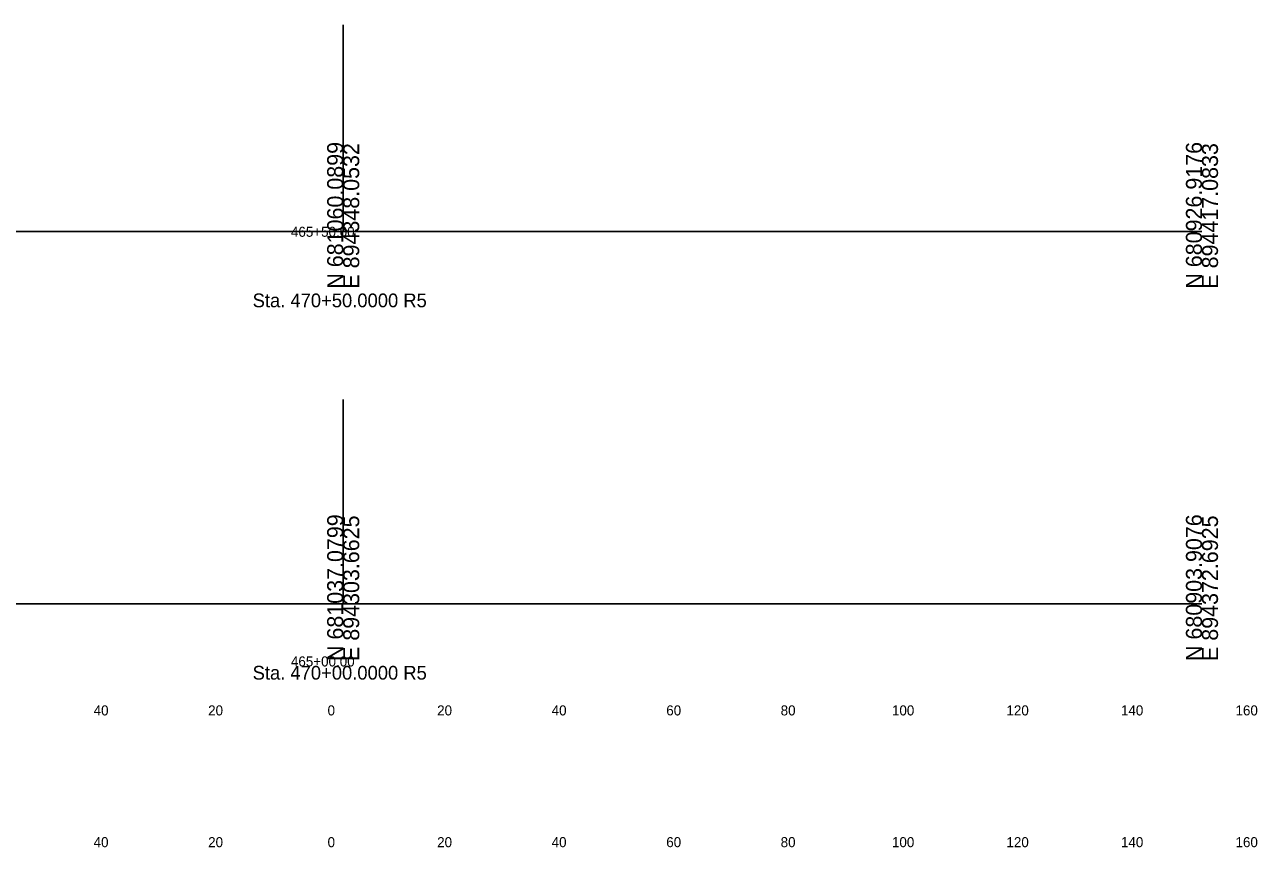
# Model space of a CAD drawing. Extents: x 21059 to 22955, y 6470 to 17494.
# Drawn here: x 21589.2 to 21804.5, y 9442.3 to 9585.9 of the extents above; entities that cross this region are included whole.
import ezdxf

# ---------------------------------------------------------------- set-up
doc = ezdxf.new("R2010")
doc.units = 0
for name, color, linetype in [('Draft_XS_Text', 7, 'Continuous'), ('DTM CONTOURS_MAJOR', 7, 'Continuous'), ('SLOPE_STAKES_FILL', 7, 'Continuous'), ('X_PROFILES_1', 7, 'Continuous')]:
    doc.layers.add(name, color=color, linetype=linetype)

msp = doc.modelspace()

# ---------------------------------------------------------------- linework, layer by layer
at = {"layer": 'DTM CONTOURS_MAJOR'}
for p, q in [((21644.84, 9549.84), (21644.84, 9585.92)), ((21494.84, 9549.84), (21644.84, 9549.84)), ((21644.84, 9549.84), (21794.84, 9549.84)), ((21644.84, 9484.84), (21644.84, 9520.47)), ((21494.84, 9484.84), (21644.84, 9484.84)), ((21644.84, 9484.84), (21794.84, 9484.84))]:
    msp.add_line(p, q, dxfattribs=at)

# ---------------------------------------------------------------- texts
at = {"layer": 'Draft_XS_Text'}
for s, p in [('  40  ', (21599.95, 9465.34)), ('  20  ', (21619.95, 9465.34)), ('  0  ', (21640.81, 9465.34)), ('  0  ', (21640.81, 9465.34)), ('  20  ', (21659.95, 9465.34)), ('  40  ', (21679.95, 9465.34)), ('  60  ', (21699.97, 9465.34)), ('  80  ', (21719.95, 9465.34)), ('  100  ', (21739.39, 9465.34)), ('  120  ', (21759.39, 9465.34)), ('  140  ', (21779.39, 9465.34)), ('  160  ', (21799.4, 9465.34)), ('  40  ', (21599.95, 9442.34)), ('  20  ', (21619.95, 9442.34)), ('  0  ', (21640.81, 9442.34)), ('  0  ', (21640.81, 9442.34)), ('  20  ', (21659.95, 9442.34)), ('  40  ', (21679.95, 9442.34)), ('  60  ', (21699.97, 9442.34)), ('  80  ', (21719.95, 9442.34)), ('  100  ', (21739.39, 9442.34)), ('  120  ', (21759.39, 9442.34)), ('  140  ', (21779.39, 9442.34)), ('  160  ', (21799.4, 9442.34))]:
    msp.add_text(s, height=1.75, dxfattribs=at).set_placement(p)
at = {"layer": 'DTM CONTOURS_MAJOR'}
for s, p in [('N 681060.0899', (21644.84, 9539.84)), ('E 894348.0532', (21647.64, 9539.84)), ('N 680926.9176', (21794.84, 9539.84)), ('E 894417.0833', (21797.64, 9539.84)), ('N 681037.0799', (21644.84, 9474.84)), ('E 894303.6625', (21647.64, 9474.84)), ('N 680903.9076', (21794.84, 9474.84)), ('E 894372.6925', (21797.64, 9474.84))]:
    msp.add_text(s, height=2.8, rotation=90, dxfattribs=at).set_placement(p)
at = {"layer": 'SLOPE_STAKES_FILL'}
for s, p in [('  465+50.00  ', (21634.41, 9548.89)), ('  465+00.00  ', (21634.41, 9473.89))]:
    msp.add_text(s, height=1.75, dxfattribs=at).set_placement(p)
at = {"layer": 'X_PROFILES_1'}
for s, p in [('Sta. 470+50.0000 R5', (21629.02, 9536.59)), ('Sta. 470+00.0000 R5', (21629.02, 9471.59))]:
    msp.add_text(s, height=2.4, dxfattribs=at).set_placement(p)

doc.saveas('drawing.dxf')
